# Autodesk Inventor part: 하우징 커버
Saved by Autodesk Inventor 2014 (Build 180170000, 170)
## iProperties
Created: 2026-05
Part Number: 하우징 커버
Material: 알루미늄 6061
Document SubType Name: Modeling
Designer: dg
Density: 2.71 g/cm^3
Appearance: 알루미늄 - 평지
Mass: 96.266 g
Surface Area: 121.399 cm^2
Volume: 35.5225 cm^3
Author: jhkim
Creation Date: 2026-04-23
Sending System: Autodesk Inventor 2027
Preprocessor: ST-DEVELOPER v20.1
Author: dg
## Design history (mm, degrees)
node "하우징 커버1"
node "솔리드1"
node "기준1"
